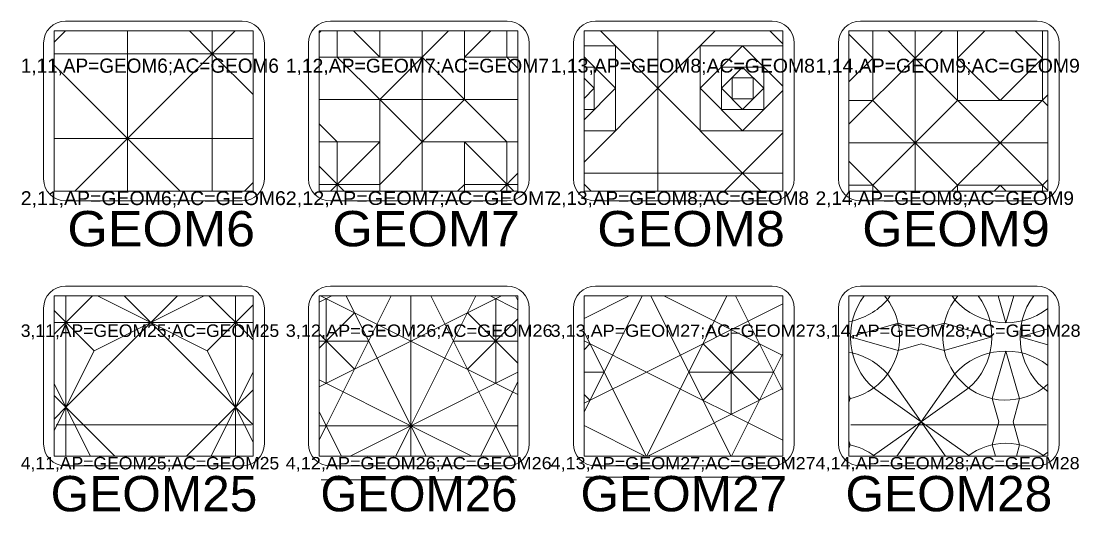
# Model space of a CAD drawing. Extents: x 95935 to 95946.4, y 95971.2 to 95974.7.
# Drawn here: x 95941.035 to 95943.432, y 95973.621 to 95974.732 of the extents above; entities that cross this region are included whole.
import ezdxf
from ezdxf.enums import TextEntityAlignment as Align

# ---------------------------------------------------------------- set-up
doc = ezdxf.new("R2010")
doc.units = 0
doc.header["$LTSCALE"] = 0.032
for name, color, linetype, lineweight in [('1', 7, 'Continuous', 13), ('2', 7, 'Continuous', 13), ('25', 7, 'Continuous', 13), ('6', 7, 'Continuous', 13), ('63', 7, 'Continuous', 13)]:
    doc.layers.add(name, color=color, linetype=linetype, lineweight=lineweight)
doc.layers.add('20', color=7, linetype='Continuous')

msp = doc.modelspace()

# ---------------------------------------------------------------- linework, layer by layer
at = {"layer": '1'}
for p, q in [((95941.1357, 95974.7318), (95941.5357, 95974.7318)), ((95941.7357, 95974.7318), (95942.1357, 95974.7318)), ((95942.3357, 95974.7318), (95942.7357, 95974.7318)), ((95942.9357, 95974.7318), (95943.3357, 95974.7318)), ((95941.0857, 95974.3747), (95941.0857, 95974.6818)), ((95941.5857, 95974.6818), (95941.5857, 95974.3747)), ((95941.6857, 95974.3747), (95941.6857, 95974.6818)), ((95942.1857, 95974.6818), (95942.1857, 95974.3747)), ((95942.2857, 95974.3747), (95942.2857, 95974.6818)), ((95942.7857, 95974.6818), (95942.7857, 95974.3747)), ((95942.8857, 95974.3747), (95942.8857, 95974.6818)), ((95943.3857, 95974.6818), (95943.3857, 95974.3747)), ((95941.5357, 95974.3247), (95941.1357, 95974.3247)), ((95942.1357, 95974.3247), (95941.7357, 95974.3247)), ((95942.7357, 95974.3247), (95942.3357, 95974.3247)), ((95943.3357, 95974.3247), (95942.9357, 95974.3247)), ((95941.1357, 95974.1318), (95941.5357, 95974.1318)), ((95941.7357, 95974.1318), (95942.1357, 95974.1318)), ((95942.3357, 95974.1318), (95942.7357, 95974.1318)), ((95942.9357, 95974.1318), (95943.3357, 95974.1318)), ((95941.0857, 95973.7747), (95941.0857, 95974.0818)), ((95941.5857, 95974.0818), (95941.5857, 95973.7747)), ((95941.6857, 95973.7747), (95941.6857, 95974.0818)), ((95942.1857, 95974.0818), (95942.1857, 95973.7747)), ((95942.2857, 95973.7747), (95942.2857, 95974.0818)), ((95942.7857, 95974.0818), (95942.7857, 95973.7747)), ((95942.8857, 95973.7747), (95942.8857, 95974.0818)), ((95943.3857, 95974.0818), (95943.3857, 95973.7747)), ((95941.5357, 95973.7247), (95941.1357, 95973.7247)), ((95942.1357, 95973.7247), (95941.7357, 95973.7247)), ((95942.7357, 95973.7247), (95942.3357, 95973.7247)), ((95943.3357, 95973.7247), (95942.9357, 95973.7247))]:
    msp.add_line(p, q, dxfattribs=at)
for centre, start, end in [((95941.1357, 95974.6818), 90, 180), ((95941.5357, 95974.6818), 0, 90), ((95941.7357, 95974.6818), 90, 180), ((95942.1357, 95974.6818), 0, 90), ((95942.3357, 95974.6818), 90, 180), ((95942.7357, 95974.6818), 0, 90), ((95942.9357, 95974.6818), 90, 180), ((95943.3357, 95974.6818), 0, 90), ((95941.1357, 95974.3747), 180, 270), ((95941.5357, 95974.3747), 270, 0), ((95941.7357, 95974.3747), 180, 270), ((95942.1357, 95974.3747), 270, 0), ((95942.3357, 95974.3747), 180, 270), ((95942.7357, 95974.3747), 270, 0), ((95942.9357, 95974.3747), 180, 270), ((95943.3357, 95974.3747), 270, 0), ((95941.1357, 95974.0818), 90, 180), ((95941.5357, 95974.0818), 0, 90), ((95941.7357, 95974.0818), 90, 180), ((95942.1357, 95974.0818), 0, 90), ((95942.3357, 95974.0818), 90, 180), ((95942.7357, 95974.0818), 0, 90), ((95942.9357, 95974.0818), 90, 180), ((95943.3357, 95974.0818), 0, 90), ((95941.1357, 95973.7747), 180, 270), ((95941.5357, 95973.7747), 270, 0), ((95941.7357, 95973.7747), 180, 270), ((95942.1357, 95973.7747), 270, 0), ((95942.3357, 95973.7747), 180, 270), ((95942.7357, 95973.7747), 270, 0), ((95942.9357, 95973.7747), 180, 270), ((95943.3357, 95973.7747), 270, 0)]:
    msp.add_arc(centre, 0.05, start, end, dxfattribs=at)
at = {"layer": '2'}
for points in [[(95941.5601, 95974.7099), (95941.1097, 95974.7099), (95941.1097, 95974.3468), (95941.5601, 95974.3468)], [(95942.1601, 95974.7099), (95941.7097, 95974.7099), (95941.7097, 95974.3468), (95942.1601, 95974.3468)], [(95942.7601, 95974.7099), (95942.3097, 95974.7099), (95942.3097, 95974.3468), (95942.7601, 95974.3468)], [(95943.3601, 95974.7099), (95942.9097, 95974.7099), (95942.9097, 95974.3468), (95943.3601, 95974.3468)], [(95941.5601, 95974.1099), (95941.1097, 95974.1099), (95941.1097, 95973.7468), (95941.5601, 95973.7468)], [(95942.1601, 95974.1099), (95941.7097, 95974.1099), (95941.7097, 95973.7468), (95942.1601, 95973.7468)], [(95942.7601, 95974.1099), (95942.3097, 95974.1099), (95942.3097, 95973.7468), (95942.7601, 95973.7468)], [(95943.3601, 95974.1099), (95942.9097, 95974.1099), (95942.9097, 95973.7468), (95943.3601, 95973.7468)]]:
    msp.add_lwpolyline(points, close=True, dxfattribs=at)
at = {"layer": '25'}
for p, q in [((95941.5569, 95973.8178), (95941.1141, 95973.8178)), ((95943.3569, 95973.8178), (95942.9141, 95973.8178)), ((95942.7569, 95973.6996), (95942.3141, 95973.6996)), ((95942.1569, 95973.6934), (95941.7141, 95973.6934))]:
    msp.add_line(p, q, dxfattribs=at)
at = {"layer": '6'}
for p, q in [((95941.1355, 95974.7099), (95941.1097, 95974.6841)), ((95941.2757, 95974.7099), (95941.2757, 95974.3468)), ((95941.4677, 95974.6581), (95941.4159, 95974.7099)), ((95941.4677, 95974.7099), (95941.4677, 95974.3468)), ((95941.7145, 95974.7099), (95941.7097, 95974.7051)), ((95941.7509, 95974.7099), (95941.7509, 95974.6503)), ((95941.7873, 95974.7099), (95941.8469, 95974.6503)), ((95941.8469, 95974.7099), (95941.8469, 95974.6503)), ((95941.9429, 95974.7099), (95941.9429, 95974.3468)), ((95942.0025, 95974.7099), (95941.9429, 95974.6503)), ((95942.0389, 95974.5543), (95942.0389, 95974.7099)), ((95942.0985, 95974.7099), (95942.0389, 95974.6503)), ((95942.1349, 95974.7099), (95942.1349, 95974.6503)), ((95942.4768, 95974.7099), (95942.4768, 95974.3468)), ((95942.4768, 95974.5798), (95942.6069, 95974.7099)), ((95942.7601, 95974.6805), (95942.7307, 95974.7099)), ((95943.0598, 95974.7099), (95943.0598, 95974.3468)), ((95943.1213, 95974.7099), (95943.0598, 95974.6484)), ((95943.1558, 95974.7099), (95943.1558, 95974.5524)), ((95943.2173, 95974.7099), (95943.1558, 95974.6484)), ((95943.3478, 95974.6484), (95943.2863, 95974.7099)), ((95943.3478, 95974.5524), (95943.3478, 95974.7099)), ((95942.3808, 95974.6758), (95942.3097, 95974.6758)), ((95942.3808, 95974.4838), (95942.3808, 95974.6758)), ((95942.5728, 95974.6758), (95942.5728, 95974.4838)), ((95942.7601, 95974.6758), (95942.5728, 95974.6758)), ((95942.7601, 95974.5845), (95942.6688, 95974.6758)), ((95941.1097, 95974.6581), (95941.5601, 95974.6581)), ((95941.2757, 95974.4661), (95941.4677, 95974.6581)), ((95941.9429, 95974.6503), (95941.7097, 95974.6503)), ((95941.9429, 95974.6503), (95942.0389, 95974.5543)), ((95942.1601, 95974.6503), (95942.0389, 95974.6503)), ((95942.1349, 95974.6503), (95942.1601, 95974.6251)), ((95943.0598, 95974.6484), (95943.2518, 95974.4564)), ((95941.1097, 95974.6321), (95941.2757, 95974.4661)), ((95942.3328, 95974.6278), (95942.3097, 95974.6278)), ((95942.3328, 95974.5318), (95942.3328, 95974.6278)), ((95942.4768, 95974.5798), (95942.6688, 95974.3878)), ((95942.6688, 95974.4838), (95942.7601, 95974.5751)), ((95943.2518, 95974.4564), (95943.3601, 95974.5647)), ((95941.7097, 95974.5543), (95942.1601, 95974.5543)), ((95941.8469, 95974.5543), (95941.8469, 95974.3468)), ((95942.9638, 95974.5524), (95943.0598, 95974.4564)), ((95943.1558, 95974.5524), (95943.0598, 95974.4564)), ((95943.1558, 95974.5524), (95943.3478, 95974.5524)), ((95943.3478, 95974.5524), (95943.3601, 95974.5401)), ((95942.3097, 95974.5318), (95942.3328, 95974.5318)), ((95941.7097, 95974.4995), (95941.7509, 95974.4583)), ((95942.3097, 95974.4838), (95942.3808, 95974.4838)), ((95942.5728, 95974.4838), (95942.7601, 95974.4838)), ((95941.1097, 95974.4661), (95941.5601, 95974.4661)), ((95941.2757, 95974.4661), (95941.1564, 95974.3468)), ((95941.395, 95974.3468), (95941.2757, 95974.4661)), ((95941.7097, 95974.4583), (95941.8469, 95974.4583)), ((95941.8469, 95974.4583), (95941.7354, 95974.3468)), ((95941.7509, 95974.4583), (95941.7509, 95974.3468)), ((95941.9429, 95974.4583), (95942.1601, 95974.4583)), ((95942.1349, 95974.4583), (95942.1349, 95974.3468)), ((95942.9097, 95974.4564), (95943.3601, 95974.4564)), ((95942.9638, 95974.3604), (95943.0598, 95974.4564)), ((95943.1558, 95974.3604), (95943.0598, 95974.4564)), ((95943.2518, 95974.4564), (95943.1422, 95974.3468)), ((95943.3601, 95974.3481), (95943.2518, 95974.4564)), ((95941.7097, 95974.4035), (95941.7664, 95974.3468)), ((95942.9774, 95974.3468), (95942.9097, 95974.4145)), ((95942.1601, 95974.3875), (95942.1194, 95974.3468)), ((95942.3097, 95974.3878), (95942.7601, 95974.3878)), ((95942.7098, 95974.3468), (95942.6688, 95974.3878)), ((95943.3478, 95974.3604), (95943.3601, 95974.3727)), ((95941.5601, 95974.3665), (95941.5404, 95974.3468)), ((95941.7097, 95974.3623), (95941.8469, 95974.3623)), ((95942.0389, 95974.3623), (95942.0234, 95974.3468)), ((95942.0389, 95974.3623), (95942.1601, 95974.3623)), ((95942.3258, 95974.3468), (95942.3097, 95974.3629)), ((95943.3478, 95974.3604), (95943.1558, 95974.3604)), ((95943.1558, 95974.3604), (95943.1558, 95974.3468)), ((95943.2518, 95974.3604), (95943.2382, 95974.3468)), ((95943.2654, 95974.3468), (95943.2518, 95974.3604)), ((95943.3478, 95974.3468), (95943.3478, 95974.3604)), ((95941.1968, 95974.1099), (95941.1097, 95974.0228)), ((95941.1365, 95974.1099), (95941.1365, 95973.7468)), ((95941.3285, 95974.0496), (95941.2079, 95974.1099)), ((95941.3285, 95974.0496), (95941.2682, 95974.1099)), ((95941.3888, 95974.1099), (95941.3285, 95974.0496)), ((95941.4491, 95974.1099), (95941.3285, 95974.0496)), ((95941.4602, 95974.1099), (95941.5601, 95974.01)), ((95941.5205, 95974.1099), (95941.5205, 95973.7468)), ((95941.7384, 95974.1099), (95941.7097, 95974.0956)), ((95941.9178, 95974.1099), (95941.9178, 95973.7468)), ((95942.1601, 95974.0785), (95942.0972, 95974.1099)), ((95942.1601, 95974.0991), (95942.1547, 95974.1099)), ((95942.4121, 95974.1099), (95942.3097, 95974.0587)), ((95942.3097, 95973.8466), (95942.4414, 95974.1099)), ((95942.6334, 95974.1099), (95942.4518, 95973.7468)), ((95942.4609, 95974.1099), (95942.6424, 95973.7468)), ((95942.7601, 95973.9749), (95942.4901, 95974.1099)), ((95942.7601, 95973.8954), (95942.6529, 95974.1099)), ((95942.9968, 95974.1008), (95943.0032, 95974.1099)), ((95943.1432, 95974.1099), (95943.1496, 95974.1008)), ((95943.2476, 95974.1099), (95943.2652, 95974.0489)), ((95943.2828, 95974.1099), (95943.2652, 95974.0489)), ((95941.5601, 95974.0892), (95941.4565, 95973.9856)), ((95941.7258, 95974.1036), (95941.7258, 95973.9116)), ((95942.1098, 95974.1036), (95942.1098, 95973.9116)), ((95941.1097, 95974.0764), (95941.2005, 95973.9856)), ((95941.7898, 95974.0716), (95941.7097, 95973.9915)), ((95942.0458, 95974.0716), (95942.1601, 95973.9573)), ((95941.1097, 95974.0496), (95941.5601, 95974.0496)), ((95941.1365, 95973.8576), (95941.3285, 95974.0496)), ((95942.1601, 95974.0579), (95942.0458, 95973.9436)), ((95943.0209, 95974.0479), (95942.9132, 95974.0169)), ((95943.0209, 95974.0479), (95943.0732, 95974.0329)), ((95943.1255, 95974.0479), (95943.0732, 95974.0329)), ((95943.1255, 95974.0479), (95943.2332, 95974.0169)), ((95943.3601, 95974.035), (95943.2972, 95974.0169)), ((95941.7097, 95974.0237), (95941.7898, 95973.9436)), ((95942.4504, 95973.7468), (95942.3097, 95974.0282)), ((95942.6431, 95974.0334), (95942.6431, 95973.8414)), ((95943.0209, 95973.9859), (95942.9132, 95974.0169)), ((95943.1255, 95973.9859), (95943.2332, 95974.0169)), ((95943.3601, 95973.9988), (95943.2972, 95974.0169)), ((95941.7097, 95974.0076), (95941.8218, 95974.0076)), ((95942.0138, 95974.0076), (95942.1601, 95974.0076)), ((95942.3231, 95974.0014), (95942.3097, 95973.988)), ((95942.7071, 95974.0014), (95942.5791, 95973.8734)), ((95942.5791, 95974.0014), (95942.7071, 95973.8734)), ((95943.0209, 95973.9859), (95943.0732, 95974.0009)), ((95943.1255, 95973.9859), (95943.0732, 95974.0009)), ((95942.6438, 95973.7468), (95942.7601, 95973.9794)), ((95943.2342, 95973.8772), (95943.2652, 95973.9849)), ((95943.2962, 95973.8772), (95943.2652, 95973.9849)), ((95941.5205, 95973.8576), (95941.5601, 95973.9368)), ((95942.3097, 95973.9374), (95942.3551, 95973.9374)), ((95942.5471, 95973.9374), (95942.7391, 95973.9374)), ((95941.1097, 95973.9112), (95941.1365, 95973.8576)), ((95941.5205, 95973.8576), (95941.5601, 95973.8972)), ((95942.4539, 95973.7468), (95942.7601, 95973.8999)), ((95943.3491, 95973.9013), (95943.3601, 95973.8935)), ((95941.1097, 95973.8844), (95941.1365, 95973.8576)), ((95942.3097, 95973.8868), (95942.3231, 95973.8734)), ((95942.9122, 95973.8772), (95942.9097, 95973.8859)), ((95942.9122, 95973.8772), (95942.9097, 95973.8685)), ((95943.2342, 95973.8772), (95943.2492, 95973.8249)), ((95943.2962, 95973.8772), (95943.2812, 95973.8249)), ((95941.1365, 95973.8576), (95941.1097, 95973.8308)), ((95941.1919, 95973.7468), (95941.1365, 95973.8576)), ((95941.5205, 95973.8576), (95941.4097, 95973.7468)), ((95941.5601, 95973.7784), (95941.5205, 95973.8576)), ((95943.0732, 95973.8249), (95942.9651, 95973.7485)), ((95943.018, 95973.7468), (95943.0732, 95973.8249)), ((95943.1813, 95973.7485), (95943.0732, 95973.8249)), ((95943.0732, 95973.8249), (95943.1284, 95973.7468)), ((95943.2342, 95973.7726), (95943.2492, 95973.8249)), ((95943.2962, 95973.7726), (95943.2812, 95973.8249)), ((95941.7097, 95973.8156), (95942.1601, 95973.8156)), ((95941.9178, 95973.8156), (95941.7802, 95973.7468)), ((95941.8834, 95973.7468), (95941.9178, 95973.8156)), ((95942.3097, 95973.8161), (95942.4483, 95973.7468)), ((95942.9122, 95973.7726), (95942.9097, 95973.7813)), ((95942.9122, 95973.7726), (95942.9097, 95973.7639)), ((95943.2342, 95973.7726), (95943.2416, 95973.7468)), ((95943.2962, 95973.7726), (95943.2888, 95973.7468)), ((95943.3601, 95973.7563), (95943.3491, 95973.7485))]:
    msp.add_line(p, q, dxfattribs=at)
for points in [[(95941.5195, 95974.7099), (95941.4677, 95974.6581), (95941.5601, 95974.5657)], [(95942.3097, 95974.4127), (95942.4768, 95974.5798), (95942.3467, 95974.7099)], [(95942.9097, 95974.4983), (95943.0598, 95974.6484), (95942.9983, 95974.7099)], [(95942.9097, 95974.5524), (95942.9638, 95974.5524), (95942.9638, 95974.7099)], [(95942.9097, 95974.5943), (95942.9638, 95974.6484), (95942.9097, 95974.7025)], [(95942.6688, 95974.6758), (95942.5728, 95974.5798), (95942.6688, 95974.4838)], [(95941.7509, 95974.6503), (95941.8469, 95974.5543), (95941.9429, 95974.6503)], [(95942.3097, 95974.5087), (95942.3808, 95974.5798), (95942.3097, 95974.6509)], [(95943.1558, 95974.6484), (95943.2518, 95974.5524), (95943.3478, 95974.6484)], [(95942.3097, 95974.5567), (95942.3328, 95974.5798), (95942.3097, 95974.6029)], [(95941.8469, 95974.3623), (95941.9429, 95974.4583), (95941.8469, 95974.5543)], [(95941.9429, 95974.4583), (95942.0389, 95974.5543), (95942.1349, 95974.4583)], [(95942.6278, 95974.3468), (95942.6688, 95974.3878), (95942.7601, 95974.4791)], [(95942.0389, 95974.3468), (95942.0389, 95974.4583), (95942.1504, 95974.3468)], [(95942.9638, 95974.3468), (95942.9638, 95974.3604), (95942.9097, 95974.3604)], [(95941.7097, 95973.9197), (95941.9178, 95973.8156), (95941.7707, 95974.1099)], [(95941.7097, 95973.9036), (95941.9178, 95974.0076), (95941.7132, 95974.1099)], [(95941.7097, 95973.8478), (95941.7258, 95973.8156), (95941.873, 95974.1099)], [(95942.1224, 95974.1099), (95941.9178, 95974.0076), (95942.1601, 95973.8865)], [(95942.065, 95974.1099), (95941.9178, 95973.8156), (95942.1601, 95973.9368)], [(95941.9627, 95974.1099), (95942.1098, 95973.8156), (95942.1601, 95973.9162)], [(95942.7601, 95974.0919), (95942.4511, 95973.9374), (95942.7601, 95973.7829)], [(95941.1365, 95973.8576), (95941.2005, 95973.9856), (95941.3285, 95974.0496), (95941.5205, 95973.8576)], [(95941.3285, 95974.0496), (95941.4565, 95973.9856), (95941.5205, 95973.8576)], [(95942.3097, 95973.8667), (95942.4511, 95973.9374), (95942.3097, 95974.0081)], [(95942.9651, 95973.9013), (95943.0732, 95973.8249), (95942.9968, 95973.933)], [(95943.1496, 95973.933), (95943.0732, 95973.8249), (95943.1813, 95973.9013)], [(95941.2473, 95973.7468), (95941.1365, 95973.8576), (95941.1097, 95973.804)], [(95941.5601, 95973.818), (95941.5205, 95973.8576), (95941.4651, 95973.7468)], [(95941.7602, 95973.7468), (95941.7258, 95973.8156), (95941.7097, 95973.7834)], [(95942.0554, 95973.7468), (95941.9178, 95973.8156), (95941.9522, 95973.7468)], [(95942.1442, 95973.7468), (95942.1098, 95973.8156), (95942.0754, 95973.7468)]]:
    msp.add_lwpolyline(points, dxfattribs=at)
for points in [[(95942.6208, 95974.6278), (95942.6208, 95974.5318), (95942.7168, 95974.5318), (95942.7168, 95974.6278)], [(95942.6688, 95974.6278), (95942.6208, 95974.5798), (95942.6688, 95974.5318), (95942.7168, 95974.5798)], [(95942.6448, 95974.6038), (95942.6448, 95974.5558), (95942.6928, 95974.5558), (95942.6928, 95974.6038)]]:
    msp.add_lwpolyline(points, close=True, dxfattribs=at)
for centre, radius, start, end in [((95942.8812, 95974.0169), 0.1431, 281.4872, 40.5308), ((95943.0679, 95974.0169), 0.1547, 143.0374, 228.3596), ((95943.2652, 95974.0169), 0.1431, 139.4692, 311.5393), ((95943.0785, 95974.0169), 0.1547, 311.6403, 36.9626), ((95943.4519, 95974.0169), 0.1547, 143.0374, 228.3596), ((95942.8812, 95974.2036), 0.1547, 280.6184, 318.3596), ((95943.2652, 95974.2036), 0.1547, 221.6403, 307.8486), ((95942.8812, 95973.8302), 0.1547, 41.6403, 79.3816), ((95943.2652, 95973.8302), 0.1547, 52.1514, 138.3596), ((95942.8812, 95973.6329), 0.1431, 52.7404, 78.5127), ((95943.2652, 95973.6329), 0.1431, 52.7404, 127.2596), ((95943.0679, 95973.6329), 0.1547, 131.6403, 132.5725), ((95943.0785, 95973.6329), 0.1547, 47.4275, 48.3596), ((95943.4519, 95973.6329), 0.1547, 131.6403, 132.5725)]:
    msp.add_arc(centre, radius, start, end, dxfattribs=at)

# ---------------------------------------------------------------- texts
at = {"layer": '20'}
for s, width, p in [(' GEOM6', 1.1, (95941.3358, 95974.222)), (' GEOM7', 1.1, (95941.9358, 95974.222)), (' GEOM8', 1.1, (95942.5357, 95974.222)), (' GEOM9', 1.1, (95943.1358, 95974.222)), ('GEOM25', 1.05, (95941.3357, 95973.622)), ('GEOM27', 1.05, (95942.5357, 95973.622)), ('GEOM28', 1.05, (95943.1358, 95973.622))]:
    msp.add_text(s, height=0.08, dxfattribs=dict(at, width=width)).set_placement(p, align=Align.CENTER)
msp.add_text('GEOM26', height=0.08, dxfattribs=at).set_placement((95941.9358, 95973.622), align=Align.CENTER)
at = {"layer": '63'}
msp.add_text('1,11,AP=GEOM6;AC=GEOM6', height=0.0321, dxfattribs=at).set_placement((95941.0341, 95974.615))
for s, height, width, p in [('1,12,AP=GEOM7;AC=GEOM7', 0.0312, 1.05, (95941.6341, 95974.6155)), ('1,13,AP=GEOM8;AC=GEOM8', 0.0313, 1.05, (95942.2341, 95974.6154)), ('1,14,AP=GEOM9;AC=GEOM9', 0.0313, 1.05, (95942.8341, 95974.6154)), ('2,11,AP=GEOM6;AC=GEOM6', 0.0314, 1.05, (95941.0341, 95974.3154)), ('2,12,AP=GEOM7;AC=GEOM7', 0.0305, 1.1, (95941.6341, 95974.3158)), ('2,13,AP=GEOM8;AC=GEOM8', 0.0306, 1.05, (95942.2341, 95974.3158)), ('2,14,AP=GEOM9;AC=GEOM9', 0.0306, 1.05, (95942.8341, 95974.3158)), ('3,11,AP=GEOM25;AC=GEOM25', 0.0283, 1.05, (95941.0341, 95974.0169)), ('3,12,AP=GEOM26;AC=GEOM26', 0.0279, 1.1, (95941.6341, 95974.0171)), ('3,13,AP=GEOM27;AC=GEOM27', 0.0277, 1.1, (95942.2341, 95974.0172)), ('3,14,AP=GEOM28;AC=GEOM28', 0.0277, 1.1, (95942.8341, 95974.0172)), ('4,11,AP=GEOM25;AC=GEOM25', 0.0283, 1.05, (95941.0341, 95973.7169)), ('4,12,AP=GEOM26;AC=GEOM26', 0.0278, 1.1, (95941.6341, 95973.7172)), ('4,13,AP=GEOM27;AC=GEOM27', 0.0277, 1.1, (95942.2341, 95973.7172)), ('4,14,AP=GEOM28;AC=GEOM28', 0.0276, 1.1, (95942.8341, 95973.7173))]:
    msp.add_text(s, height=height, dxfattribs=dict(at, width=width)).set_placement(p)

doc.saveas('drawing.dxf')
